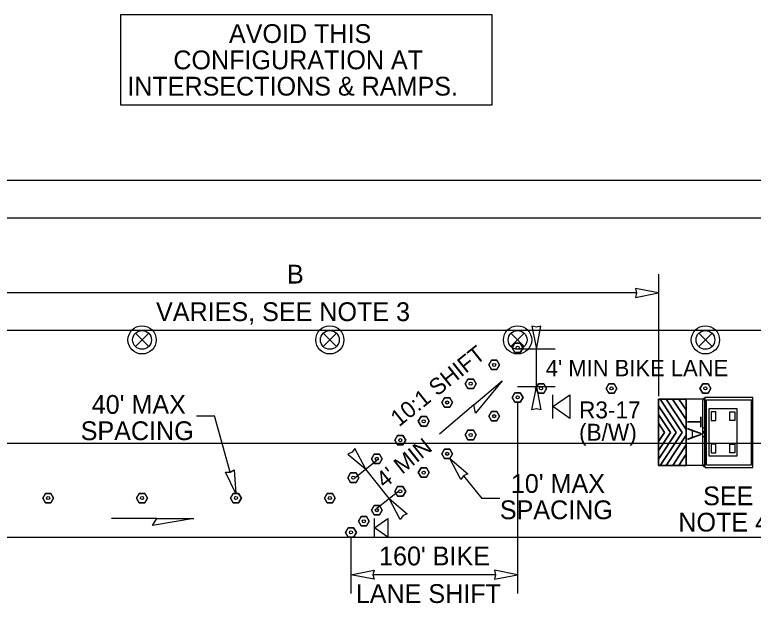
# Model space of a CAD drawing. Extents: x 99958 to 100136, y 99935 to 100013.
# Drawn here: x 100027.548 to 100030.694, y 99944.955 to 99947.46 of the extents above; entities that cross this region are included whole.
import ezdxf

# ---------------------------------------------------------------- set-up
doc = ezdxf.new("R2010")
doc.units = 0
for name, color, linetype in [('RD_ED_ShoulderPavedEdge', 7, 'Continuous'), ('RD_MK_LineEdgeWhite', 7, 'Continuous'), ('RD_MK_LineEdgeYellow', 7, 'Continuous'), ('RD_MK_LineLane', 7, 'Continuous'), ('SH_TI_Tables', 7, 'Continuous'), ('TR_SN_ConstructionSigns', 7, 'Continuous'), ('TR_WZ_PortableSignMountBlk-Org', 7, 'Continuous'), ('TR_WZ_PortableSignMountBlk-Wht', 7, 'Continuous'), ('TR_WZ_TrafficSafetyDrum', 7, 'Continuous'), ('TR_WZ_TransportableAttenuator', 7, 'Continuous'), ('TR_WZ_TubularMarker', 7, 'Continuous'), ('TR_WZ_WorkZoneDetails', 7, 'Continuous'), ('TR_WZ_WorkZoneTextCurrent', 7, 'Continuous')]:
    doc.layers.add(name, color=color, linetype=linetype)

msp = doc.modelspace()

# ---------------------------------------------------------------- linework, layer by layer
at = {"layer": 'RD_ED_ShoulderPavedEdge'}
for p, q in [((100021.7753, 99946.7557), (100035.62, 99946.7557)), ((100021.7753, 99945.2357), (100035.62, 99945.2357))]:
    msp.add_line(p, q, dxfattribs=at)
at = {"layer": 'RD_MK_LineEdgeWhite'}
msp.add_line((100021.7753, 99945.6357), (100035.62, 99945.6357), dxfattribs=at)
at = {"layer": 'RD_MK_LineEdgeYellow'}
msp.add_line((100021.7753, 99946.5957), (100035.62, 99946.5957), dxfattribs=at)
at = {"layer": 'RD_MK_LineLane'}
msp.add_lwpolyline([(100035.62, 99946.1157), (100021.7753, 99946.1157)], dxfattribs=at)
at = {"layer": 'SH_TI_Tables'}
msp.add_lwpolyline([(100027.998, 99947.0757), (100029.5825, 99947.0757), (100029.5825, 99947.4597), (100027.998, 99947.4597)], close=True, dxfattribs=at)
at = {"layer": 'TR_WZ_PortableSignMountBlk-Org'}
msp.add_line((100029.0803, 99945.2357), (100029.0803, 99945.3157), dxfattribs=at)
msp.add_lwpolyline([(100029.0803, 99945.2757), (100029.1377, 99945.3157), (100029.1377, 99945.2357)], close=True, dxfattribs=at)
at = {"layer": 'TR_WZ_PortableSignMountBlk-Wht'}
msp.add_line((100029.8403, 99945.7416), (100029.8403, 99945.8416), dxfattribs=at)
msp.add_lwpolyline([(100029.8403, 99945.7916), (100029.9121, 99945.8416), (100029.9121, 99945.7416)], close=True, dxfattribs=at)
at = {"layer": 'TR_WZ_TrafficSafetyDrum'}
for p, q in [((100028.062, 99946.104), (100028.1186, 99946.0474)), ((100028.1186, 99946.104), (100028.062, 99946.0474)), ((100028.062, 99946.104), (100028.1186, 99946.0474)), ((100028.1186, 99946.104), (100028.062, 99946.0474)), ((100028.862, 99946.104), (100028.9186, 99946.0474)), ((100028.9186, 99946.104), (100028.862, 99946.0474)), ((100028.862, 99946.104), (100028.9186, 99946.0474)), ((100028.9186, 99946.104), (100028.862, 99946.0474)), ((100029.662, 99946.104), (100029.7186, 99946.0474)), ((100029.7186, 99946.104), (100029.662, 99946.0474)), ((100029.662, 99946.104), (100029.7186, 99946.0474)), ((100029.7186, 99946.104), (100029.662, 99946.0474)), ((100030.462, 99946.104), (100030.5186, 99946.0474)), ((100030.5186, 99946.104), (100030.462, 99946.0474)), ((100030.462, 99946.104), (100030.5186, 99946.0474)), ((100030.5186, 99946.104), (100030.462, 99946.0474))]:
    msp.add_line(p, q, dxfattribs=at)
for centre, radius in [((100028.0903, 99946.0757), 0.06), ((100028.0903, 99946.0757), 0.06), ((100028.0903, 99946.0757), 0.06), ((100028.0903, 99946.0757), 0.06), ((100028.8903, 99946.0757), 0.06), ((100028.8903, 99946.0757), 0.06), ((100028.8903, 99946.0757), 0.06), ((100028.8903, 99946.0757), 0.06), ((100029.6903, 99946.0757), 0.06), ((100029.6903, 99946.0757), 0.06), ((100029.6903, 99946.0757), 0.06), ((100029.6903, 99946.0757), 0.06), ((100030.4903, 99946.0757), 0.06), ((100030.4903, 99946.0757), 0.06), ((100030.4903, 99946.0757), 0.06), ((100030.4903, 99946.0757), 0.06), ((100028.0903, 99946.0757), 0.04), ((100028.0903, 99946.0757), 0.04), ((100028.8903, 99946.0757), 0.04), ((100028.8903, 99946.0757), 0.04), ((100029.6903, 99946.0757), 0.04), ((100029.6903, 99946.0757), 0.04), ((100030.4903, 99946.0757), 0.04), ((100030.4903, 99946.0757), 0.04)]:
    msp.add_circle(centre, radius, dxfattribs=at)
at = {"layer": 'TR_WZ_TransportableAttenuator'}
for p, q in [((100030.3231, 99945.8231), (100030.298, 99945.8231)), ((100030.298, 99945.8231), (100030.3918, 99945.6821)), ((100030.3918, 99945.6821), (100030.298, 99945.8231)), ((100030.298, 99945.8231), (100030.3231, 99945.8231)), ((100030.4085, 99945.6948), (100030.3231, 99945.8231)), ((100030.3231, 99945.8231), (100030.4085, 99945.6948)), ((100030.3777, 99945.8231), (100030.3507, 99945.8231)), ((100030.3507, 99945.8231), (100030.4085, 99945.7363)), ((100030.4085, 99945.7363), (100030.3507, 99945.8231)), ((100030.3507, 99945.8231), (100030.3777, 99945.8231)), ((100030.4085, 99945.7777), (100030.3777, 99945.8231)), ((100030.3777, 99945.8231), (100030.4085, 99945.7777)), ((100030.4891, 99945.8229), (100030.4085, 99945.8229)), ((100030.4085, 99945.8229), (100030.4085, 99945.5413)), ((100030.4796, 99945.5465), (100030.4796, 99945.8183)), ((100030.484, 99945.8275), (100030.4884, 99945.8275)), ((100030.4884, 99945.5373), (100030.4884, 99945.8275)), ((100030.4891, 99945.8324), (100030.6927, 99945.8324)), ((100030.4891, 99945.5324), (100030.4891, 99945.8324)), ((100030.4891, 99945.5418), (100030.4891, 99945.8229)), ((100030.4949, 99945.5444), (100030.4949, 99945.8204)), ((100030.4949, 99945.8204), (100030.6869, 99945.8204)), ((100030.6869, 99945.5444), (100030.6869, 99945.8204)), ((100030.6927, 99945.5324), (100030.6927, 99945.8324)), ((100030.3656, 99945.6813), (100030.2903, 99945.7945)), ((100030.2903, 99945.7945), (100030.2903, 99945.7577)), ((100030.2903, 99945.7577), (100030.2903, 99945.7945)), ((100030.2903, 99945.7945), (100030.3656, 99945.6813)), ((100030.2903, 99945.7577), (100030.3414, 99945.6809)), ((100030.3414, 99945.6809), (100030.2903, 99945.7577)), ((100030.4085, 99945.7363), (100030.4085, 99945.7777)), ((100030.4085, 99945.7777), (100030.4085, 99945.7363)), ((100030.3164, 99945.682), (100030.2903, 99945.7212)), ((100030.2903, 99945.7212), (100030.2903, 99945.6432)), ((100030.2903, 99945.7212), (100030.3164, 99945.682)), ((100030.2903, 99945.6432), (100030.2903, 99945.7212)), ((100030.4085, 99945.6697), (100030.4085, 99945.6948)), ((100030.4085, 99945.6948), (100030.4085, 99945.6697)), ((100030.4796, 99945.7036), (100030.4884, 99945.6979)), ((100030.2903, 99945.6432), (100030.3164, 99945.682)), ((100030.3164, 99945.682), (100030.2903, 99945.6432)), ((100030.2903, 99945.5681), (100030.3656, 99945.6813)), ((100030.3656, 99945.6813), (100030.2903, 99945.5681)), ((100030.3414, 99945.6809), (100030.2903, 99945.6046)), ((100030.2903, 99945.6046), (100030.3414, 99945.6809)), ((100030.3918, 99945.6821), (100030.2981, 99945.5413)), ((100030.2981, 99945.5413), (100030.3918, 99945.6821)), ((100030.3236, 99945.5413), (100030.4085, 99945.6697)), ((100030.4085, 99945.6697), (100030.3236, 99945.5413)), ((100030.4796, 99945.6613), (100030.4884, 99945.6669)), ((100030.482, 99945.6824), (100030.4861, 99945.6824)), ((100030.484, 99945.6782), (100030.484, 99945.6866)), ((100030.4085, 99945.6282), (100030.3513, 99945.5413)), ((100030.3513, 99945.5413), (100030.4085, 99945.6282)), ((100030.4085, 99945.589), (100030.4085, 99945.6282)), ((100030.4085, 99945.6282), (100030.4085, 99945.589)), ((100030.2903, 99945.6046), (100030.2903, 99945.5681)), ((100030.2903, 99945.5681), (100030.2903, 99945.6046)), ((100030.3768, 99945.5413), (100030.4085, 99945.589)), ((100030.4085, 99945.589), (100030.3768, 99945.5413)), ((100030.2981, 99945.5413), (100030.3236, 99945.5413)), ((100030.3236, 99945.5413), (100030.2981, 99945.5413)), ((100030.3513, 99945.5413), (100030.3768, 99945.5413)), ((100030.3768, 99945.5413), (100030.3513, 99945.5413)), ((100030.4891, 99945.5413), (100030.4085, 99945.5413)), ((100030.484, 99945.5373), (100030.4884, 99945.5373)), ((100030.4949, 99945.5444), (100030.6869, 99945.5444)), ((100030.4891, 99945.5324), (100030.6927, 99945.5324))]:
    msp.add_line(p, q, dxfattribs=at)
for points in [[(100030.4085, 99945.8231), (100030.2903, 99945.8231), (100030.2903, 99945.5413), (100030.4085, 99945.5413)], [(100030.5049, 99945.5824), (100030.6252, 99945.5824), (100030.6252, 99945.7824), (100030.5049, 99945.7824)], [(100030.515, 99945.7324), (100030.535, 99945.7324), (100030.535, 99945.7699), (100030.515, 99945.7699)], [(100030.6152, 99945.7324), (100030.5951, 99945.7324), (100030.5951, 99945.7699), (100030.6152, 99945.7699)], [(100030.515, 99945.5949), (100030.535, 99945.5949), (100030.535, 99945.6324), (100030.515, 99945.6324)], [(100030.6152, 99945.5949), (100030.5951, 99945.5949), (100030.5951, 99945.6324), (100030.6152, 99945.6324)]]:
    msp.add_lwpolyline(points, close=True, dxfattribs=at)
msp.add_lwpolyline([(100030.4085, 99945.5413), (100030.2903, 99945.5413), (100030.2903, 99945.8231), (100030.4085, 99945.8229)], dxfattribs=at)
for centre, major_axis, start_param, end_param in [((100030.484, 99945.8183), (0, 0.00916), 0, 1.570796), ((100030.484, 99945.5465), (0, -0.00916), 4.712389, 6.283185)]:
    msp.add_ellipse(centre, major_axis=major_axis, ratio=0.482618, start_param=start_param, end_param=end_param, dxfattribs=at)
msp.add_ellipse((100030.484, 99945.6824), major_axis=(0, -0.00423), ratio=0.482618, dxfattribs=at)
at = {"layer": 'TR_WZ_TubularMarker'}
for points in [[(100029.6672, 99946.0424), (100029.6787, 99946.0624), (100029.7018, 99946.0624), (100029.7134, 99946.0424), (100029.7018, 99946.0224), (100029.6787, 99946.0224)], [(100029.5672, 99945.969), (100029.5787, 99945.989), (100029.6018, 99945.989), (100029.6134, 99945.969), (100029.6018, 99945.949), (100029.5787, 99945.949)], [(100029.4672, 99945.889), (100029.4787, 99945.909), (100029.5018, 99945.909), (100029.5134, 99945.889), (100029.5018, 99945.869), (100029.4787, 99945.869)], [(100029.7672, 99945.8691), (100029.7787, 99945.8891), (100029.8018, 99945.8891), (100029.8134, 99945.8691), (100029.8018, 99945.8491), (100029.7787, 99945.8491)], [(100030.0672, 99945.8691), (100030.0787, 99945.8891), (100030.1018, 99945.8891), (100030.1134, 99945.8691), (100030.1018, 99945.8491), (100030.0787, 99945.8491)], [(100030.4672, 99945.8691), (100030.4787, 99945.8891), (100030.5018, 99945.8891), (100030.5134, 99945.8691), (100030.5018, 99945.8491), (100030.4787, 99945.8491)], [(100029.6672, 99945.8308), (100029.6787, 99945.8508), (100029.7018, 99945.8508), (100029.7134, 99945.8308), (100029.7018, 99945.8108), (100029.6787, 99945.8108)], [(100029.3672, 99945.809), (100029.3787, 99945.829), (100029.4018, 99945.829), (100029.4134, 99945.809), (100029.4018, 99945.789), (100029.3787, 99945.789)], [(100029.5672, 99945.7508), (100029.5787, 99945.7708), (100029.6018, 99945.7708), (100029.6134, 99945.7508), (100029.6018, 99945.7308), (100029.5787, 99945.7308)], [(100029.2672, 99945.729), (100029.2787, 99945.749), (100029.3018, 99945.749), (100029.3134, 99945.729), (100029.3018, 99945.709), (100029.2787, 99945.709)], [(100029.4672, 99945.6708), (100029.4787, 99945.6908), (100029.5018, 99945.6908), (100029.5134, 99945.6708), (100029.5018, 99945.6508), (100029.4787, 99945.6508)], [(100029.1672, 99945.649), (100029.1787, 99945.669), (100029.2018, 99945.669), (100029.2134, 99945.649), (100029.2018, 99945.629), (100029.1787, 99945.629)], [(100029.3672, 99945.5908), (100029.3787, 99945.6108), (100029.4018, 99945.6108), (100029.4134, 99945.5908), (100029.4018, 99945.5708), (100029.3787, 99945.5708)], [(100029.0672, 99945.5691), (100029.0787, 99945.5891), (100029.1018, 99945.5891), (100029.1134, 99945.5691), (100029.1018, 99945.5491), (100029.0787, 99945.5491)], [(100028.9672, 99945.4891), (100028.9787, 99945.5091), (100029.0018, 99945.5091), (100029.0134, 99945.4891), (100029.0018, 99945.4691), (100028.9787, 99945.4691)], [(100029.2672, 99945.5108), (100029.2787, 99945.5308), (100029.3018, 99945.5308), (100029.3134, 99945.5108), (100029.3018, 99945.4908), (100029.2787, 99945.4908)], [(100029.1672, 99945.4308), (100029.1787, 99945.4508), (100029.2018, 99945.4508), (100029.2134, 99945.4308), (100029.2018, 99945.4108), (100029.1787, 99945.4108)], [(100027.6672, 99945.4024), (100027.6787, 99945.4224), (100027.7018, 99945.4224), (100027.7134, 99945.4024), (100027.7018, 99945.3824), (100027.6787, 99945.3824)], [(100028.0672, 99945.4024), (100028.0787, 99945.4224), (100028.1018, 99945.4224), (100028.1134, 99945.4024), (100028.1018, 99945.3824), (100028.0787, 99945.3824)], [(100028.4672, 99945.4024), (100028.4787, 99945.4224), (100028.5018, 99945.4224), (100028.5134, 99945.4024), (100028.5018, 99945.3824), (100028.4787, 99945.3824)], [(100028.8672, 99945.4024), (100028.8787, 99945.4224), (100028.9018, 99945.4224), (100028.9134, 99945.4024), (100028.9018, 99945.3824), (100028.8787, 99945.3824)], [(100029.0672, 99945.3508), (100029.0787, 99945.3708), (100029.1018, 99945.3708), (100029.1134, 99945.3508), (100029.1018, 99945.3308), (100029.0787, 99945.3308)], [(100029.0122, 99945.3035), (100029.0237, 99945.3235), (100029.0468, 99945.3235), (100029.0584, 99945.3035), (100029.0468, 99945.2835), (100029.0237, 99945.2835)], [(100028.9572, 99945.2562), (100028.9687, 99945.2762), (100028.9918, 99945.2762), (100029.0034, 99945.2562), (100028.9918, 99945.2362), (100028.9687, 99945.2362)]]:
    msp.add_lwpolyline(points, close=True, dxfattribs=at)
for points in [[(100029.6787, 99946.0224), (100029.7018, 99946.0224), (100029.7134, 99946.0424), (100029.7018, 99946.0624), (100029.6787, 99946.0624), (100029.6672, 99946.0424), (100029.6787, 99946.0224)], [(100029.5787, 99945.949), (100029.6018, 99945.949), (100029.6134, 99945.969), (100029.6018, 99945.989), (100029.5787, 99945.989), (100029.5672, 99945.969), (100029.5787, 99945.949)], [(100029.4787, 99945.869), (100029.5018, 99945.869), (100029.5134, 99945.889), (100029.5018, 99945.909), (100029.4787, 99945.909), (100029.4672, 99945.889), (100029.4787, 99945.869)], [(100029.7787, 99945.8491), (100029.8018, 99945.8491), (100029.8134, 99945.8691), (100029.8018, 99945.8891), (100029.7787, 99945.8891), (100029.7672, 99945.8691), (100029.7787, 99945.8491)], [(100030.0787, 99945.8491), (100030.1018, 99945.8491), (100030.1134, 99945.8691), (100030.1018, 99945.8891), (100030.0787, 99945.8891), (100030.0672, 99945.8691), (100030.0787, 99945.8491)], [(100030.4787, 99945.8491), (100030.5018, 99945.8491), (100030.5134, 99945.8691), (100030.5018, 99945.8891), (100030.4787, 99945.8891), (100030.4672, 99945.8691), (100030.4787, 99945.8491)], [(100029.6787, 99945.8108), (100029.7018, 99945.8108), (100029.7134, 99945.8308), (100029.7018, 99945.8508), (100029.6787, 99945.8508), (100029.6672, 99945.8308), (100029.6787, 99945.8108)], [(100029.3787, 99945.789), (100029.4018, 99945.789), (100029.4134, 99945.809), (100029.4018, 99945.829), (100029.3787, 99945.829), (100029.3672, 99945.809), (100029.3787, 99945.789)], [(100029.5787, 99945.7308), (100029.6018, 99945.7308), (100029.6134, 99945.7508), (100029.6018, 99945.7708), (100029.5787, 99945.7708), (100029.5672, 99945.7508), (100029.5787, 99945.7308)], [(100029.2787, 99945.709), (100029.3018, 99945.709), (100029.3134, 99945.729), (100029.3018, 99945.749), (100029.2787, 99945.749), (100029.2672, 99945.729), (100029.2787, 99945.709)], [(100029.4787, 99945.6508), (100029.5018, 99945.6508), (100029.5134, 99945.6708), (100029.5018, 99945.6908), (100029.4787, 99945.6908), (100029.4672, 99945.6708), (100029.4787, 99945.6508)], [(100029.1787, 99945.629), (100029.2018, 99945.629), (100029.2134, 99945.649), (100029.2018, 99945.669), (100029.1787, 99945.669), (100029.1672, 99945.649), (100029.1787, 99945.629)], [(100029.3787, 99945.5708), (100029.4018, 99945.5708), (100029.4134, 99945.5908), (100029.4018, 99945.6108), (100029.3787, 99945.6108), (100029.3672, 99945.5908), (100029.3787, 99945.5708)], [(100029.0787, 99945.5491), (100029.1018, 99945.5491), (100029.1134, 99945.5691), (100029.1018, 99945.5891), (100029.0787, 99945.5891), (100029.0672, 99945.5691), (100029.0787, 99945.5491)], [(100028.9787, 99945.4691), (100029.0018, 99945.4691), (100029.0134, 99945.4891), (100029.0018, 99945.5091), (100028.9787, 99945.5091), (100028.9672, 99945.4891), (100028.9787, 99945.4691)], [(100029.2787, 99945.4908), (100029.3018, 99945.4908), (100029.3134, 99945.5108), (100029.3018, 99945.5308), (100029.2787, 99945.5308), (100029.2672, 99945.5108), (100029.2787, 99945.4908)], [(100029.1787, 99945.4108), (100029.2018, 99945.4108), (100029.2134, 99945.4308), (100029.2018, 99945.4508), (100029.1787, 99945.4508), (100029.1672, 99945.4308), (100029.1787, 99945.4108)], [(100027.6787, 99945.3824), (100027.7018, 99945.3824), (100027.7134, 99945.4024), (100027.7018, 99945.4224), (100027.6787, 99945.4224), (100027.6672, 99945.4024), (100027.6787, 99945.3824)], [(100028.0787, 99945.3824), (100028.1018, 99945.3824), (100028.1134, 99945.4024), (100028.1018, 99945.4224), (100028.0787, 99945.4224), (100028.0672, 99945.4024), (100028.0787, 99945.3824)], [(100028.4787, 99945.3824), (100028.5018, 99945.3824), (100028.5134, 99945.4024), (100028.5018, 99945.4224), (100028.4787, 99945.4224), (100028.4672, 99945.4024), (100028.4787, 99945.3824)], [(100028.8787, 99945.3824), (100028.9018, 99945.3824), (100028.9134, 99945.4024), (100028.9018, 99945.4224), (100028.8787, 99945.4224), (100028.8672, 99945.4024), (100028.8787, 99945.3824)], [(100029.0787, 99945.3308), (100029.1018, 99945.3308), (100029.1134, 99945.3508), (100029.1018, 99945.3708), (100029.0787, 99945.3708), (100029.0672, 99945.3508), (100029.0787, 99945.3308)], [(100029.0237, 99945.2835), (100029.0468, 99945.2835), (100029.0584, 99945.3035), (100029.0468, 99945.3235), (100029.0237, 99945.3235), (100029.0122, 99945.3035), (100029.0237, 99945.2835)], [(100028.9687, 99945.2362), (100028.9918, 99945.2362), (100029.0034, 99945.2562), (100028.9918, 99945.2762), (100028.9687, 99945.2762), (100028.9572, 99945.2562), (100028.9687, 99945.2362)]]:
    msp.add_lwpolyline(points, dxfattribs=at)
for centre in [(100029.6903, 99946.0424), (100029.5903, 99945.969), (100029.4903, 99945.889), (100029.7903, 99945.8691), (100030.0903, 99945.8691), (100030.4903, 99945.8691), (100029.6903, 99945.8308), (100029.3903, 99945.809), (100029.5903, 99945.7508), (100029.2903, 99945.729), (100029.4903, 99945.6708), (100029.1903, 99945.649), (100029.3903, 99945.5908), (100029.0903, 99945.5691), (100029.2903, 99945.5108), (100028.9903, 99945.4891), (100027.6903, 99945.4024), (100028.0903, 99945.4024), (100028.4903, 99945.4024), (100028.8903, 99945.4024), (100029.1903, 99945.4308), (100029.0903, 99945.3508), (100029.0353, 99945.3035), (100028.9803, 99945.2562)]:
    msp.add_circle(centre, 0.00667, dxfattribs=at)
at = {"layer": 'TR_WZ_WorkZoneDetails'}
for p, q in [((100030.2903, 99946.3557), (100030.2903, 99945.8362)), ((100030.1965, 99946.2757), (100027.384, 99946.2757)), ((100029.8503, 99946.0357), (100029.6903, 99946.0357)), ((100029.7703, 99945.8757), (100029.7703, 99946.0357)), ((100029.8503, 99945.8757), (100029.6903, 99945.8757)), ((100029.5044, 99945.7992), (100029.3573, 99945.6744)), ((100029.6903, 99945.8108), (100029.6903, 99945.6357)), ((100028.3224, 99945.7529), (100028.3986, 99945.7529)), ((100028.4652, 99945.5127), (100028.3987, 99945.7529)), ((100029.6903, 99945.6357), (100029.6903, 99945.2357)), ((100029.0903, 99945.5624), (100028.9968, 99945.4876)), ((100029.1435, 99945.4), (100029.0435, 99945.525)), ((100029.4604, 99945.4976), (100029.5382, 99945.4003)), ((100029.1838, 99945.4323), (100029.0903, 99945.3575)), ((100029.6145, 99945.4003), (100029.5382, 99945.4003)), ((100028.1531, 99945.3157), (100027.9602, 99945.3157)), ((100028.9803, 99945.2357), (100028.9803, 99944.9957)), ((100029.6903, 99945.2357), (100029.6903, 99944.9957)), ((100029.5965, 99945.0757), (100029.074, 99945.0757))]:
    msp.add_line(p, q, dxfattribs=at)
for points in [[(100030.2903, 99946.2757), (100030.192, 99946.295), (100030.1965, 99946.2757), (100030.192, 99946.2565)], [(100029.7703, 99946.0357), (100029.7896, 99946.134), (100029.7703, 99946.1295), (100029.751, 99946.134)], [(100029.6244, 99945.9008), (100029.5108, 99945.7641), (100029.5044, 99945.7992)], [(100029.7703, 99945.8757), (100029.7896, 99945.7774), (100029.7703, 99945.782), (100029.751, 99945.7774)], [(100029.0435, 99945.525), (100028.9972, 99945.6138), (100028.985, 99945.5982), (100028.9671, 99945.5897)], [(100029.4018, 99945.5708), (100029.4782, 99945.506), (100029.4603, 99945.4976), (100029.4481, 99945.482)], [(100028.4903, 99945.4224), (100028.4455, 99945.512), (100028.4653, 99945.5127), (100028.4827, 99945.5223)], [(100029.1435, 99945.4), (100029.2199, 99945.3353), (100029.202, 99945.3269), (100029.1898, 99945.3113)], [(100028.3103, 99945.3157), (100028.1353, 99945.2849), (100028.1531, 99945.3157)], [(100028.9803, 99945.0757), (100029.0786, 99945.095), (100029.074, 99945.0757), (100029.0786, 99945.0565)], [(100029.6903, 99945.0757), (100029.592, 99945.095), (100029.5965, 99945.0757), (100029.592, 99945.0565)]]:
    msp.add_lwpolyline(points, close=True, dxfattribs=at)

# ---------------------------------------------------------------- texts
at = {"layer": 'SH_TI_Tables'}
for s, p in [('AVOID THIS', (100028.4605, 99947.3397)), ('CONFIGURATION AT ', (100028.2237, 99947.2277)), ('INTERSECTIONS & RAMPS.', (100028.0274, 99947.1157))]:
    msp.add_text(s, height=0.08, dxfattribs=at).set_placement(p)
at = {"layer": 'TR_SN_ConstructionSigns'}
for s, p in [('R3-17', (100029.9521, 99945.7416)), ('(B/W)', (100029.9521, 99945.6466))]:
    msp.add_text(s, height=0.072, rotation=360, dxfattribs=at).set_placement(p)
at = {"layer": 'TR_WZ_TransportableAttenuator'}
msp.add_text('TA', height=0.06013, rotation=270, dxfattribs=at).set_placement((100030.414, 99945.751))
at = {"layer": 'TR_WZ_WorkZoneTextCurrent'}
for s, height, rotation, p in [('B', 0.08, 360, (100028.7079, 99946.3157)), ('VARIES, SEE NOTE 3', 0.08, 360, (100028.15, 99946.1557)), ('10:1 SHIFT', 0.07, 38.6583, (100029.1848, 99945.7031)), ("4' MIN", 0.07, 38.6583, (100029.1232, 99945.4414)), ("160' BIKE", 0.08, 360, (100029.1001, 99945.1157)), ('LANE SHIFT', 0.08, 360, (100029.0009, 99944.9557))]:
    msp.add_text(s, height=height, rotation=rotation, dxfattribs=at).set_placement(p)
for s, height, p in [("4' MIN BIKE LANE", 0.07, (100029.8103, 99945.9207)), ("40' MAX", 0.08, (100027.876, 99945.7609)), ('SPACING', 0.08, (100027.8289, 99945.6489)), ("10' MAX", 0.08, (100029.6616, 99945.4243)), ('SEE', 0.08, (100030.4807, 99945.3717)), ('SPACING', 0.08, (100029.6145, 99945.3123)), ('NOTE 4', 0.08, (100030.3751, 99945.2597))]:
    msp.add_text(s, height=height, dxfattribs=at).set_placement(p)

doc.saveas('drawing.dxf')
